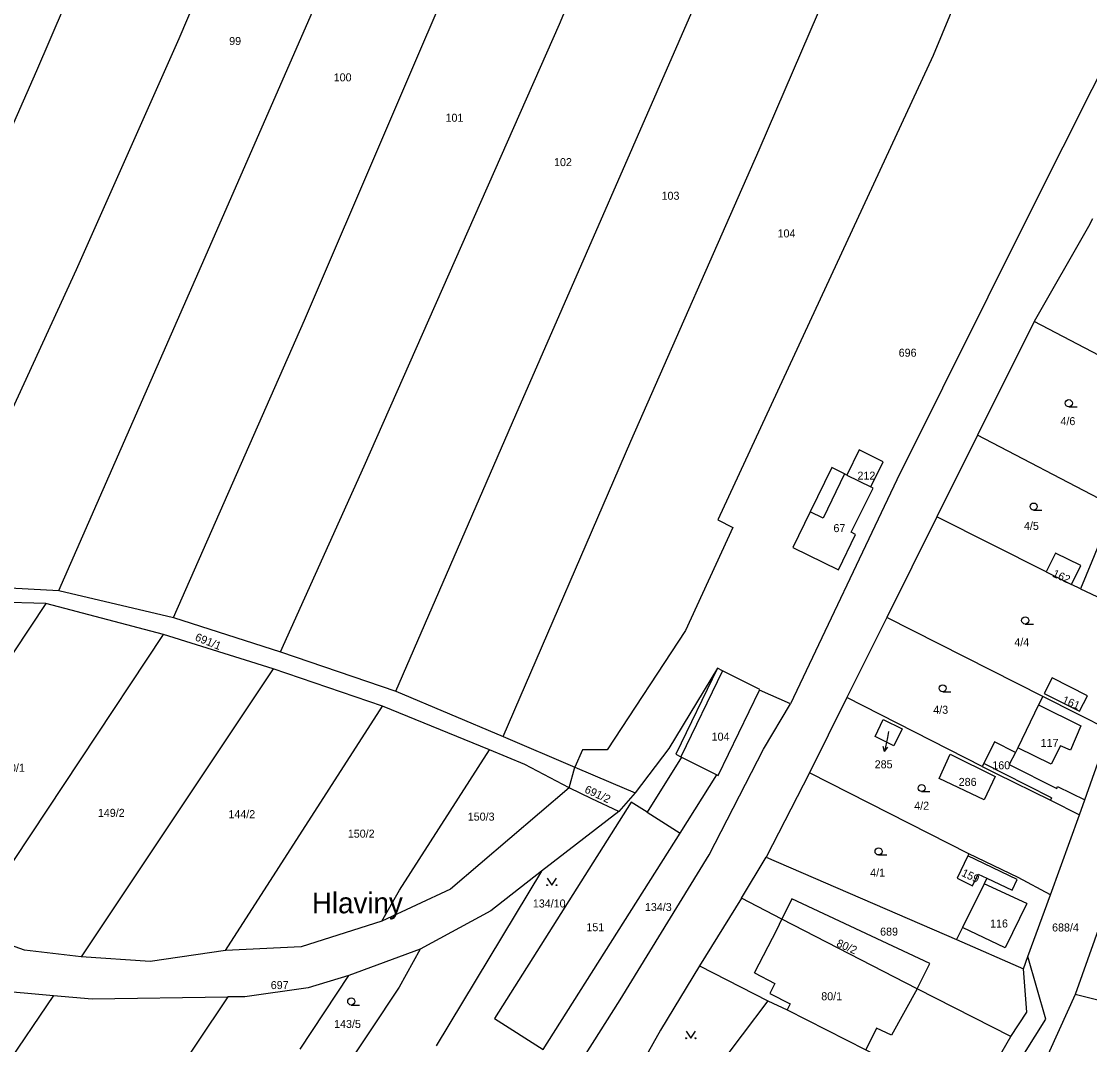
# Model space of a CAD drawing. Extents: x -747333 to -743907, y -1134120 to -1130051.
# Drawn here: x -746336.6 to -746109.8, y -1131640.4 to -1131423.1 of the extents above; entities that cross this region are included whole.
import ezdxf

# ---------------------------------------------------------------- set-up
doc = ezdxf.new("R2010")
doc.units = 0
for name, color, linetype in [('Hranice parcel', 7, 'Continuous'), ('Parcelní čísla', 7, 'Continuous'), ('Pop  PČ popisy', 7, 'Continuous'), ('Vnitřní kresba', 7, 'Continuous'), ('Značky kultur', 7, 'Continuous')]:
    doc.layers.add(name, color=color, linetype=linetype)

msp = doc.modelspace()

# ---------------------------------------------------------------- linework, layer by layer
at = {"layer": 'Hranice parcel'}
for p, q in [((-746121.6, -1131486.86), (-746133.59, -1131510.98)), ((-746101.76, -1131497.26), (-746121.6, -1131486.86)), ((-746133.59, -1131510.98), (-746142.23, -1131528.33)), ((-746106.2, -1131525.3), (-746133.59, -1131510.98)), ((-746161.36, -1131519.45), (-746156.25, -1131521.97)), ((-746142.23, -1131528.33), (-746152.87, -1131549.67)), ((-746119.01, -1131540), (-746142.23, -1131528.33)), ((-746119.01, -1131540), (-746113.64, -1131542.65)), ((-746355.61, -1131542.43), (-746328.65, -1131543.97)), ((-746111.71, -1131543.57), (-746113.64, -1131542.65)), ((-746111.71, -1131543.57), (-746096.91, -1131550.67)), ((-746331.46, -1131546.72), (-746359.57, -1131545.85)), ((-746328.65, -1131543.97), (-746304.3, -1131549.68)), ((-746331.46, -1131546.72), (-746366.12, -1131598.98)), ((-746306.49, -1131553.28), (-746331.46, -1131546.72)), ((-746304.3, -1131549.68), (-746281.63, -1131556.99)), ((-746152.87, -1131549.67), (-746161.36, -1131566.66)), ((-746119.76, -1131566.48), (-746152.87, -1131549.67)), ((-746348.04, -1131615.98), (-746306.49, -1131553.28)), ((-746283.17, -1131560.59), (-746306.49, -1131553.28)), ((-746281.63, -1131556.99), (-746257.15, -1131565.35)), ((-746283.17, -1131560.59), (-746323.97, -1131621.69)), ((-746259.92, -1131568.5), (-746283.17, -1131560.59)), ((-746257.15, -1131565.35), (-746234.36, -1131574.92)), ((-746173.33, -1131568.01), (-746179.87, -1131565.13)), ((-746293.31, -1131620.35), (-746259.92, -1131568.5)), ((-746237.25, -1131577.76), (-746259.92, -1131568.5)), ((-746161.36, -1131566.66), (-746169.3, -1131582.67)), ((-746132.61, -1131581.31), (-746161.36, -1131566.66)), ((-746234.36, -1131574.92), (-746219.1, -1131581.44)), ((-746110.85, -1131588.4), (-746105.62, -1131573.59)), ((-746196.48, -1131579.32), (-746188.95, -1131583.07)), ((-746220.35, -1131585.87), (-746219.1, -1131581.44)), ((-746169.3, -1131582.67), (-746178.46, -1131600.58)), ((-746135.43, -1131599.84), (-746169.3, -1131582.67)), ((-746206.27, -1131586.91), (-746209.75, -1131590.87)), ((-746111.97, -1131591.58), (-746110.85, -1131588.4)), ((-746209.75, -1131590.87), (-746226.17, -1131603.55)), ((-746118.15, -1131608.57), (-746111.97, -1131591.58)), ((-746135.43, -1131599.84), (-746135.65, -1131600.29)), ((-746183.74, -1131609.25), (-746178.46, -1131600.58)), ((-746178.46, -1131600.58), (-746138.05, -1131618.07)), ((-746226.17, -1131603.55), (-746248.59, -1131640.59)), ((-746104.52, -1131606.12), (-746112.88, -1131629.7)), ((-746183.74, -1131609.25), (-746192.62, -1131623.6)), ((-746175.19, -1131613.74), (-746183.74, -1131609.25)), ((-746122.9, -1131621.67), (-746118.15, -1131608.57)), ((-746146.41, -1131628.53), (-746175.19, -1131613.74)), ((-746138.05, -1131618.07), (-746123.85, -1131624.29)), ((-746251.98, -1131620.08), (-746267.12, -1131625.65)), ((-746123.85, -1131624.29), (-746122.9, -1131621.67)), ((-746192.62, -1131623.6), (-746178.11, -1131631.02)), ((-746277.47, -1131641.33), (-746267.12, -1131625.65)), ((-746329.82, -1131629.89), (-746350.48, -1131660.43)), ((-746126.56, -1131638.66), (-746146.41, -1131628.53)), ((-746112.88, -1131629.7), (-746125.11, -1131656.77)), ((-746096.04, -1131633.97), (-746112.88, -1131629.7)), ((-746178.11, -1131631.02), (-746197.29, -1131656.44)), ((-746134.91, -1131653.16), (-746126.56, -1131638.66))]:
    msp.add_line(p, q, dxfattribs=at)
for points in [[(-746383.44, -1131540.92), (-746372.02, -1131517.94), (-746355.04, -1131482.69), (-746333.35, -1131433.58), (-746288.12, -1131328.39), (-746273.9, -1131297.53)], [(-746355.61, -1131542.43), (-746324.93, -1131475.84), (-746303.11, -1131426.75), (-746270.15, -1131349.38), (-746250.49, -1131305.53)], [(-746328.65, -1131543.97), (-746298.39, -1131474.98), (-746247.6, -1131358.82), (-746226.99, -1131313.72)], [(-746304.3, -1131549.68), (-746276.49, -1131486.57), (-746241.74, -1131405.49), (-746204.37, -1131321.72)], [(-746281.63, -1131556.99), (-746263.86, -1131517.53), (-746222.34, -1131423.75), (-746209.5, -1131392.92), (-746191.95, -1131352.1), (-746181.58, -1131329.92)], [(-746257.15, -1131565.35), (-746231.61, -1131506.69), (-746191.8, -1131415.47), (-746175.11, -1131375.93), (-746157.27, -1131340.24)], [(-746234.36, -1131574.92), (-746207.21, -1131512.24), (-746179.95, -1131450.43), (-746151.42, -1131384.21), (-746133.83, -1131347.95)], [(-746111.08, -1131353.49), (-746143.06, -1131430.4), (-746188.77, -1131528.95), (-746185.55, -1131530.56), (-746195.61, -1131552.43), (-746212.24, -1131577.79), (-746217.48, -1131577.79), (-746219.1, -1131581.44)], [(-746090.75, -1131400.54), (-746121.73, -1131462.2), (-746150.71, -1131520.43), (-746173.33, -1131568.01)], [(-746109.2, -1131465.08), (-746110.05, -1131466.67), (-746121.6, -1131486.86)], [(-746156.25, -1131521.97), (-746153.61, -1131516.62), (-746158.72, -1131514.09), (-746161.36, -1131519.45)], [(-746161.36, -1131519.45), (-746161.85, -1131519.21), (-746164.57, -1131517.87), (-746169.15, -1131527.29), (-746172.8, -1131534.8)], [(-746172.8, -1131534.8), (-746163.15, -1131539.55), (-746159.49, -1131532.04), (-746160.43, -1131531.58), (-746155.77, -1131522.21), (-746156.25, -1131521.97)], [(-746104.53, -1131526.13), (-746105.42, -1131528.29), (-746109.33, -1131537.8), (-746111.71, -1131543.57)], [(-746113.64, -1131542.65), (-746111.67, -1131538.68), (-746117.05, -1131536.03), (-746119.01, -1131540)], [(-746188.81, -1131560.47), (-746199.16, -1131577.52), (-746206.27, -1131586.91)], [(-746188.81, -1131560.47), (-746197.69, -1131578.71), (-746196.61, -1131579.25), (-746196.48, -1131579.32)], [(-746179.87, -1131565.13), (-746179.8, -1131564.99), (-746187.32, -1131561.22), (-746187.73, -1131561.01), (-746188.81, -1131560.47)], [(-746110.28, -1131566.3), (-746117.75, -1131562.51), (-746119.43, -1131565.83), (-746111.97, -1131569.59), (-746110.28, -1131566.3)], [(-746188.95, -1131583.07), (-746188.68, -1131583.2), (-746179.87, -1131565.13)], [(-746221.25, -1131649.38), (-746209.49, -1131630.87), (-746190.58, -1131600.07), (-746179.04, -1131577.6), (-746173.33, -1131568.01)], [(-746119.76, -1131566.48), (-746120.65, -1131568.25), (-746125.06, -1131577.32), (-746125.58, -1131578.32)], [(-746105.62, -1131573.59), (-746112.3, -1131570.23), (-746119.76, -1131566.48)], [(-746149.58, -1131573.32), (-746151.37, -1131576.9), (-746155.37, -1131574.98), (-746153.62, -1131571.37), (-746149.58, -1131573.32)], [(-746125.58, -1131578.32), (-746129.97, -1131576.1), (-746132.28, -1131580.66), (-746132.61, -1131581.31)], [(-746260.07, -1131614.14), (-746256.36, -1131607.58), (-746237.25, -1131577.76)], [(-746220.35, -1131585.87), (-746229.75, -1131580.92), (-746237.25, -1131577.76)], [(-746196.48, -1131579.32), (-746203.74, -1131591.04), (-746207.17, -1131588.88), (-746236.19, -1131634.81), (-746225.82, -1131641.41)], [(-746129.84, -1131583.45), (-746132.21, -1131588.4), (-746141.73, -1131583.83), (-746139.39, -1131578.66), (-746129.84, -1131583.45)], [(-746125.58, -1131578.32), (-746126.87, -1131580.87), (-746116.8, -1131585.98), (-746116.6, -1131585.54), (-746110.85, -1131588.4)], [(-746219.1, -1131581.44), (-746211.45, -1131584.7), (-746206.27, -1131586.91)], [(-746132.61, -1131581.31), (-746129.63, -1131582.82), (-746118.13, -1131588.43), (-746111.97, -1131591.58)], [(-746225.82, -1131641.41), (-746196.77, -1131595.45), (-746188.95, -1131583.07)], [(-746220.35, -1131585.87), (-746245.48, -1131607.32), (-746260.07, -1131614.14)], [(-746209.75, -1131590.87), (-746215.49, -1131588.16), (-746220.35, -1131585.87)], [(-746135.65, -1131600.29), (-746137.95, -1131605), (-746134.65, -1131606.61), (-746133.46, -1131604.17), (-746131.63, -1131605.04)], [(-746131.63, -1131605.04), (-746126.28, -1131607.58), (-746125.18, -1131605.31), (-746135.65, -1131600.29)], [(-746118.15, -1131608.57), (-746124.96, -1131604.86), (-746135.43, -1131599.84)], [(-746226.17, -1131603.55), (-746236.96, -1131611.95), (-746251.98, -1131620.08)], [(-746131.63, -1131605.04), (-746132.2, -1131606.23), (-746136.79, -1131615.51), (-746138.05, -1131618.07)], [(-746146.41, -1131628.53), (-746143.73, -1131623.16), (-746173.04, -1131609.37), (-746175.19, -1131613.74)], [(-746323.97, -1131621.69), (-746335.96, -1131620.33), (-746348.04, -1131615.98)], [(-746260.07, -1131614.14), (-746277.21, -1131619.59), (-746293.31, -1131620.35)], [(-746293.31, -1131620.35), (-746309.27, -1131622.68), (-746323.97, -1131621.69)], [(-746251.98, -1131620.08), (-746256.41, -1131628.18), (-746268.75, -1131646.7)], [(-746209.77, -1131799.39), (-746188.47, -1131759.43), (-746165.71, -1131716.39), (-746153.65, -1131693.34), (-746142.41, -1131673.43), (-746130.42, -1131652.96), (-746119.1, -1131634.98), (-746122.9, -1131621.67)], [(-746192.62, -1131623.6), (-746200.96, -1131637.27), (-746207.82, -1131649.53)], [(-746126.56, -1131638.66), (-746123.16, -1131633.44), (-746123.85, -1131624.29)], [(-746357.67, -1131625.64), (-746343.19, -1131628.73), (-746329.82, -1131629.89)], [(-746267.12, -1131625.65), (-746275.72, -1131628.32), (-746289.21, -1131630.19), (-746292.81, -1131630.24)], [(-746329.82, -1131629.89), (-746321.59, -1131630.6), (-746292.81, -1131630.24)], [(-746292.81, -1131630.24), (-746318.73, -1131668.93), (-746345.52, -1131710.16)], [(-746178.11, -1131631.02), (-746174.04, -1131632.93), (-746157.34, -1131641.42), (-746134.91, -1131653.16)]]:
    msp.add_lwpolyline(points, dxfattribs=at)
at = {"layer": 'Pop  PČ popisy'}
for p, q in [((-746152.76, -1131575.18), (-746153.333, -1131578.126)), ((-746152.5, -1131573.86), (-746152.76, -1131575.18)), ((-746153.333, -1131578.126), (-746153.633, -1131577.047)), ((-746153.333, -1131578.126), (-746152.65, -1131577.238))]:
    msp.add_line(p, q, dxfattribs=at)
at = {"layer": 'Vnitřní kresba'}
for p, q in [((-746161.85, -1131519.21), (-746166.42, -1131528.62)), ((-746166.42, -1131528.62), (-746169.15, -1131527.29)), ((-746187.73, -1131561.01), (-746196.61, -1131579.25)), ((-746120.65, -1131568.25), (-746111.65, -1131572.71)), ((-746111.65, -1131572.71), (-746113.9, -1131577.84)), ((-746117.98, -1131580.83), (-746125.06, -1131577.32)), ((-746115.99, -1131576.95), (-746117.98, -1131580.83)), ((-746113.9, -1131577.84), (-746115.99, -1131576.95)), ((-746127.92, -1131582.84), (-746132.28, -1131580.66)), ((-746117.87, -1131587.95), (-746127.92, -1131582.84)), ((-746117.87, -1131587.95), (-746118.13, -1131588.43)), ((-746203.74, -1131591.04), (-746196.77, -1131595.45)), ((-746123.14, -1131610.41), (-746132.2, -1131606.23)), ((-746123.14, -1131610.41), (-746127.73, -1131619.82)), ((-746176.18, -1131615.83), (-746175.19, -1131613.74)), ((-746180.96, -1131625.14), (-746176.18, -1131615.83)), ((-746127.73, -1131619.82), (-746136.79, -1131615.51)), ((-746180.96, -1131625.14), (-746176.62, -1131627.37)), ((-746176.62, -1131627.37), (-746177.72, -1131629.52)), ((-746177.72, -1131629.52), (-746173.42, -1131631.72)), ((-746146.41, -1131628.53), (-746151.91, -1131638.33)), ((-746173.42, -1131631.72), (-746174.04, -1131632.93)), ((-746155.06, -1131636.85), (-746157.34, -1131641.42)), ((-746151.91, -1131638.33), (-746155.06, -1131636.85))]:
    msp.add_line(p, q, dxfattribs=at)
at = {"layer": 'Značky kultur'}
for p, q in [((-746114.223, -1131504.94), (-746112.473, -1131504.94)), ((-746121.693, -1131526.89), (-746119.943, -1131526.89)), ((-746123.493, -1131551.07), (-746121.743, -1131551.07)), ((-746141.003, -1131565.46), (-746139.253, -1131565.46)), ((-746145.483, -1131586.64), (-746143.733, -1131586.64)), ((-746154.623, -1131600.09), (-746152.873, -1131600.09)), ((-746266.593, -1131631.94), (-746264.843, -1131631.94))]:
    msp.add_line(p, q, dxfattribs=at)
for points in [[(-746225.01, -1131604.999), (-746224.01, -1131606.5), (-746223.01, -1131604.999)], [(-746195.5, -1131637.499), (-746194.5, -1131639), (-746193.5, -1131637.499)]]:
    msp.add_lwpolyline(points, dxfattribs=at)
for centre, radius in [((-746114.223, -1131504.19), 0.75), ((-746121.693, -1131526.14), 0.75), ((-746123.493, -1131550.32), 0.75), ((-746141.003, -1131564.71), 0.75), ((-746145.483, -1131585.89), 0.75), ((-746154.623, -1131599.34), 0.75), ((-746225.01, -1131606.499), 0.1), ((-746223.01, -1131606.499), 0.1), ((-746266.593, -1131631.19), 0.75), ((-746195.5, -1131638.999), 0.1), ((-746193.5, -1131638.999), 0.1)]:
    msp.add_circle(centre, radius, dxfattribs=at)

# ---------------------------------------------------------------- texts
at = {"layer": 'Parcelní čísla'}
for s, p in [('99', (-746292.51, -1131428.17)), ('100', (-746270.31, -1131435.88)), ('101', (-746246.57, -1131444.45)), ('102', (-746223.53, -1131453.87)), ('103', (-746200.7, -1131461.01)), ('104', (-746176.07, -1131469.01)), ('696', (-746150.35, -1131494.33)), ('4/6', (-746116, -1131508.85)), ('212', (-746159.1, -1131520.42)), ('67', (-746164.2, -1131531.56)), ('4/5', (-746123.75, -1131531.09)), ('4/4', (-746125.8, -1131555.79)), ('4/3', (-746143.01, -1131570.12)), ('104', (-746190.07, -1131575.82)), ('117', (-746120.2, -1131577.15)), ('285', (-746155.444, -1131581.693)), ('150/1', (-746341.58, -1131582.43)), ('160', (-746130.47, -1131581.9)), ('286', (-746137.604, -1131585.43)), ('4/2', (-746147.05, -1131590.49)), ('149/2', (-746320.39, -1131592)), ('144/2', (-746292.67, -1131592.28)), ('150/3', (-746241.85, -1131592.8)), ('150/2', (-746267.32, -1131596.42)), ('4/1', (-746156.41, -1131604.7)), ('134/10', (-746228.03, -1131611.24)), ('134/3', (-746204.23, -1131611.99)), ('116', (-746130.94, -1131615.49)), ('151', (-746216.66, -1131616.27)), ('689', (-746154.29, -1131617.21)), ('688/4', (-746117.78, -1131616.33)), ('697', (-746283.68, -1131628.56)), ('80/1', (-746166.79, -1131630.93)), ('143/5', (-746270.23, -1131636.81))]:
    msp.add_text(s, height=1.7, dxfattribs=at).set_placement(p)
for s, rotation, p in [('162', 336, (-746117.855, -1131540.966)), ('691/1', 338, (-746299.899, -1131554.489)), ('161', 337, (-746115.792, -1131567.802)), ('691/2', 335, (-746217.192, -1131586.758)), ('159', 335, (-746137.169, -1131604.48)), ('80/2', 336, (-746163.705, -1131619.426))]:
    msp.add_text(s, height=1.7, rotation=rotation, dxfattribs=at).set_placement(p)
at = {"layer": 'Pop  PČ popisy'}
msp.add_text('Hlaviny', height=4.4, dxfattribs=at).set_placement((-746274.938, -1131612.47))

doc.saveas('drawing.dxf')
